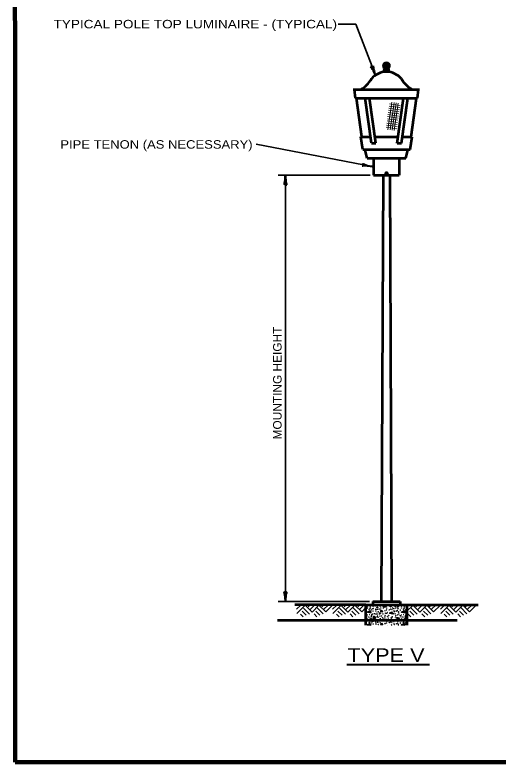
# Model space of a CAD drawing. Extents: x -20 to 693, y -19 to 435.
# Drawn here: x 28 to 170.8, y -9.1 to 211.7 of the extents above; entities that cross this region are included whole.
import ezdxf
from ezdxf.enums import TextEntityAlignment as Align

# ---------------------------------------------------------------- set-up
doc = ezdxf.new("R2010")
doc.units = 0
doc.layers.add('1', color=7, linetype='Continuous', lineweight=53)

msp = doc.modelspace()

# ---------------------------------------------------------------- hatches: boundary and pattern name
at = {"layer": '1'}
for points in [[(138.833, 196.724, 1), (136.756, 196.724, 1)], [(138.076, 164.899, 1), (137.588, 164.899, 1)]]:
    msp.add_hatch(color=256, dxfattribs=at).paths.add_polyline_path(points)

# ---------------------------------------------------------------- linework, layer by layer
at = {"layer": '1', "lineweight": 35}
for p, q in [((128.705, 209.006), (123.541, 209.006)), ((128.705, 209.006), (134.529, 193.909)), ((133.549, 166.911), (99.249, 173.552)), ((133.004, 164.369), (105.741, 164.369)), ((107.922, 38.361), (107.922, 164.369)), ((132.741, 38.361), (105.741, 38.361)), ((112.482, 37.324), (111.241, 36.083)), ((113.817, 37.324), (111.353, 34.861)), ((112.839, 35.519), (114.042, 34.315)), ((113.271, 36.421), (115.02, 34.691)), ((113.723, 37.324), (115.791, 35.255)), ((115.152, 37.324), (114.625, 36.778)), ((116.506, 37.324), (115.208, 36.026)), ((117.841, 37.324), (115.791, 35.255)), ((116.919, 35.575), (118.123, 34.372)), ((117.352, 36.478), (119.082, 34.748)), ((117.841, 37.324), (119.853, 35.312)), ((119.176, 37.324), (118.687, 36.835)), ((120.529, 37.324), (119.288, 36.083)), ((121.865, 37.324), (119.853, 35.312)), ((123.106, 37.324), (121.865, 36.083)), ((124.441, 37.324), (121.977, 34.861)), ((123.463, 35.519), (124.666, 34.315)), ((123.895, 36.421), (125.644, 34.691)), ((124.347, 37.324), (126.415, 35.255)), ((125.776, 37.324), (125.249, 36.778)), ((127.13, 37.324), (125.832, 36.026)), ((128.465, 37.324), (126.415, 35.255)), ((127.543, 35.575), (128.747, 34.372)), ((127.976, 36.478), (129.706, 34.748)), ((128.465, 37.324), (130.477, 35.312)), ((129.8, 37.324), (129.311, 36.835)), ((131.154, 37.324), (129.912, 36.083)), ((131.741, 36.576), (130.477, 35.312)), ((141.085, 36.615), (140.861, 37.361)), ((144.354, 37.324), (143.861, 36.831)), ((145.689, 37.324), (143.861, 35.496)), ((144.711, 35.519), (145.914, 34.315)), ((145.143, 36.421), (146.892, 34.691)), ((145.595, 37.324), (147.663, 35.255)), ((147.024, 37.324), (146.497, 36.778)), ((148.378, 37.324), (147.08, 36.026)), ((149.713, 37.324), (147.663, 35.255)), ((148.791, 35.575), (149.995, 34.372)), ((149.224, 36.478), (150.954, 34.748)), ((149.713, 37.324), (151.725, 35.312)), ((151.048, 37.324), (150.559, 36.835)), ((152.401, 37.324), (151.16, 36.083)), ((153.737, 37.324), (151.725, 35.312)), ((154.978, 37.324), (153.737, 36.083)), ((156.313, 37.324), (153.849, 34.861)), ((155.335, 35.519), (156.538, 34.315)), ((155.767, 36.421), (157.516, 34.691)), ((156.219, 37.324), (158.287, 35.255)), ((157.648, 37.324), (157.121, 36.778)), ((159.002, 37.324), (157.704, 36.026)), ((160.337, 37.324), (158.287, 35.255)), ((159.415, 35.575), (160.619, 34.372)), ((159.848, 36.478), (161.578, 34.748)), ((160.337, 37.324), (162.349, 35.312)), ((161.672, 37.324), (161.183, 36.835)), ((163.025, 37.324), (161.785, 36.083)), ((164.361, 37.324), (162.349, 35.312)), ((112.369, 34.654), (113.177, 33.864)), ((116.43, 34.71), (117.239, 33.901)), ((122.993, 34.654), (123.801, 33.864)), ((127.054, 34.71), (127.863, 33.901)), ((144.241, 34.654), (145.049, 33.864)), ((148.302, 34.71), (149.111, 33.901)), ((154.865, 34.654), (155.673, 33.864)), ((158.926, 34.71), (159.735, 33.901)), ((133.203, 31.361), (133.105, 31.815)), ((139.365, 31.475), (139.156, 31.361)), ((139.41, 31.361), (139.325, 31.495)), ((143.283, 31.361), (143.185, 31.815))]:
    msp.add_line(p, q, dxfattribs=at)
at = {"layer": '1'}
for p, q in [((136.851, 195.253), (138.75, 195.253)), ((136.851, 195.253), (136.851, 194.855)), ((138.75, 195.253), (138.75, 194.855)), ((127.992, 189.678), (147.609, 189.678)), ((128.625, 187.147), (128.309, 189.678)), ((146.976, 187.147), (147.293, 189.678)), ((130.522, 175.756), (128.941, 187.147)), ((133.337, 173.875), (131.496, 187.147)), ((134.614, 173.875), (132.774, 187.147)), ((140.984, 173.875), (142.827, 187.147)), ((142.262, 173.875), (144.104, 187.147)), ((145.08, 175.756), (146.66, 187.147)), ((130.831, 171.959), (130.198, 175.756)), ((130.198, 175.756), (133.076, 175.756)), ((134.354, 175.756), (141.246, 175.756)), ((142.524, 175.756), (145.403, 175.756)), ((144.77, 171.959), (145.403, 175.756)), ((133.337, 173.875), (134.614, 173.875)), ((140.984, 173.875), (142.262, 173.875)), ((130.831, 171.959), (144.77, 171.959)), ((132.086, 169.428), (131.491, 171.806)), ((143.516, 169.428), (144.11, 171.806)), ((132.086, 169.428), (143.516, 169.428)), ((134.004, 169.428), (134.004, 164.365)), ((141.598, 169.428), (141.598, 164.365)), ((134.004, 164.365), (141.598, 164.365)), ((136.781, 164.369), (136.281, 38.361)), ((138.821, 164.361), (139.321, 38.361)), ((133.741, 38.361), (141.861, 38.361)), ((133.741, 38.361), (133.741, 37.361)), ((141.861, 38.361), (141.861, 37.361)), ((131.741, 37.361), (110.741, 37.361)), ((131.741, 31.361), (131.741, 37.361)), ((143.861, 37.361), (164.861, 37.361)), ((105.614, 32.918), (158.734, 32.918))]:
    msp.add_line(p, q, dxfattribs=at)
at = {"layer": '1', "lineweight": 13}
for p, q in [((138.23, 177.835), (139.412, 185.977)), ((138.858, 177.744), (140.038, 185.886)), ((139.483, 177.654), (140.665, 185.795)), ((140.109, 177.563), (141.291, 185.705)), ((141.554, 183.109), (138.423, 183.562)), ((141.645, 183.736), (138.514, 184.189)), ((141.735, 184.362), (138.605, 184.815)), ((141.826, 184.988), (138.695, 185.441)), ((141.282, 181.231), (138.149, 181.684)), ((141.372, 181.856), (138.243, 182.311)), ((141.464, 182.483), (138.333, 182.936)), ((140.918, 178.725), (137.787, 179.179)), ((141.009, 179.351), (137.878, 179.805)), ((141.1, 179.977), (137.969, 180.431)), ((141.191, 180.604), (138.06, 181.058)), ((140.827, 178.099), (137.697, 178.553))]:
    msp.add_line(p, q, dxfattribs=at)
at = {"layer": '1', "lineweight": 40}
msp.add_line((126.043, 19.789), (150.482, 19.789), dxfattribs=at)
at = {"layer": '1', "lineweight": 158}
msp.add_line((687.723, -9.063), (28.056, -9.063), dxfattribs=at)
msp.add_lwpolyline([(687.723, 429.353), (27.973, 429.27), (28.056, -9.063)], dxfattribs=at)
at = {"layer": '1'}
for points in [[(128.625, 187.147), (132.747, 187.147), (144.124, 187.147), (146.976, 187.147)], [(131.741, 37.361), (143.861, 37.361), (143.861, 31.361)]]:
    msp.add_lwpolyline(points, dxfattribs=at)
at = {"layer": '1', "lineweight": 35}
for points in [[(133.105, 35.655), (132.165, 35.275), (133.205, 35.155), (133.105, 35.615)], [(134.575, 37.361), (133.825, 36.995), (133.877, 37.361)], [(136.465, 35.795), (136.085, 35.395), (136.665, 35.355), (136.465, 35.755)], [(141.106, 37.361), (141.625, 37.255), (141.065, 36.655)], [(143.185, 35.655), (142.245, 35.275), (143.285, 35.155), (143.185, 35.615)], [(133.985, 34.015), (134.685, 33.615), (133.825, 33.195), (133.945, 34.035)], [(139.365, 35.275), (138.705, 34.915), (139.685, 34.735), (139.325, 35.295)], [(141.085, 32.815), (140.845, 33.615), (141.625, 33.455), (141.065, 32.855)], [(133.105, 31.855), (132.165, 31.475), (133.149, 31.361)], [(136.465, 31.995), (136.085, 31.595), (136.665, 31.555), (136.465, 31.955)], [(143.185, 31.855), (142.245, 31.475), (143.229, 31.361)]]:
    msp.add_lwpolyline(points, dxfattribs=at)
for points in [[(136.745, 37.035), (137.785, 36.915), (137.105, 36.675)], [(136.745, 33.235), (137.785, 33.115), (137.105, 32.875)]]:
    msp.add_lwpolyline(points, close=True, dxfattribs=at)
for centre, radius in [((137.794, 196.724), 1.038), ((131.815, 35.852), 0.0265), ((132.146, 36.484), 0.0265), ((132.212, 37.027), 0.0265), ((132.703, 35.945), 0.0265), ((132.915, 36.258), 0.0265), ((132.994, 37.279), 0.0265), ((133.007, 36.762), 0.0265), ((133.286, 37.213), 0.0265), ((133.339, 35.905), 0.0265), ((133.617, 36.232), 0.0265), ((133.869, 35.534), 0.0265), ((133.895, 36.351), 0.0265), ((134.638, 37.067), 0.0265), ((134.664, 35.998), 0.0265), ((134.677, 36.165), 0.0265), ((134.704, 35.547), 0.0265), ((134.969, 36.669), 0.0265), ((135.168, 36.051), 0.0265), ((135.194, 36.669), 0.0265), ((135.38, 35.362), 0.0265), ((135.658, 36.179), 0.0265), ((135.89, 37.038), 0.0265), ((136.024, 35.865), 0.0265), ((136.116, 37.054), 0.0265), ((136.116, 36.457), 0.0265), ((136.925, 36.417), 0.0265), ((137.362, 35.653), 0.0265), ((137.813, 35.826), 0.0265), ((137.919, 36.338), 0.0265), ((138.356, 37.279), 0.0265), ((138.621, 35.918), 0.0265), ((138.952, 36.868), 0.0265), ((139.019, 36.112), 0.0265), ((139.271, 37.014), 0.0265), ((139.416, 35.985), 0.0265), ((139.615, 36.47), 0.0265), ((139.973, 36.271), 0.0265), ((140.039, 35.587), 0.0265), ((140.198, 35.375), 0.0265), ((140.371, 36.842), 0.0265), ((140.556, 36.417), 0.0265), ((140.715, 35.587), 0.0265), ((141.113, 35.746), 0.0265), ((141.205, 36.271), 0.0265), ((141.895, 35.852), 0.0265), ((142.226, 36.484), 0.0265), ((142.292, 37.027), 0.0265), ((142.783, 35.945), 0.0265), ((142.995, 36.258), 0.0265), ((143.074, 37.279), 0.0265), ((143.087, 36.762), 0.0265), ((143.366, 37.213), 0.0265), ((143.419, 35.905), 0.0265), ((143.697, 36.232), 0.0265), ((131.775, 34.208), 0.0265), ((132.053, 33.837), 0.0265), ((132.186, 34.434), 0.0265), ((132.212, 33.227), 0.0265), ((132.57, 33.81), 0.0265), ((132.835, 34.526), 0.0265), ((132.994, 33.479), 0.0265), ((133.233, 35.017), 0.0265), ((133.286, 33.413), 0.0265), ((133.299, 33.89), 0.0265), ((133.365, 34.195), 0.0265), ((133.471, 34.513), 0.0265), ((133.75, 34.685), 0.0265), ((134.28, 34.805), 0.0265), ((134.638, 33.267), 0.0265), ((134.73, 34.659), 0.0265), ((135.048, 34.951), 0.0265), ((135.101, 33.996), 0.0265), ((135.154, 34.553), 0.0265), ((135.327, 33.704), 0.0265), ((135.738, 34.964), 0.0265), ((135.751, 34.646), 0.0265), ((135.89, 33.238), 0.0265), ((135.91, 34.049), 0.0265), ((135.971, 34.884), 0.0265), ((136.116, 33.254), 0.0265), ((136.328, 34.102), 0.0265), ((136.66, 33.585), 0.0265), ((136.752, 34.712), 0.0265), ((137.336, 33.81), 0.0265), ((137.389, 34.208), 0.0265), ((137.468, 34.937), 0.0265), ((137.813, 34.898), 0.0265), ((138.078, 33.996), 0.0265), ((138.131, 35.136), 0.0265), ((138.356, 33.479), 0.0265), ((138.475, 34.208), 0.0265), ((139.231, 33.704), 0.0265), ((139.271, 33.214), 0.0265), ((139.642, 33.877), 0.0265), ((140.039, 34.845), 0.0265), ((140.41, 33.638), 0.0265), ((140.424, 34.752), 0.0265), ((140.543, 34.182), 0.0265), ((141.086, 34.42), 0.0265), ((141.338, 35.282), 0.0265), ((141.391, 35.282), 0.0265), ((141.457, 34.699), 0.0265), ((141.855, 34.208), 0.0265), ((142.133, 33.837), 0.0265), ((142.266, 34.434), 0.0265), ((142.292, 33.227), 0.0265), ((142.65, 33.81), 0.0265), ((142.915, 34.526), 0.0265), ((143.074, 33.479), 0.0265), ((143.313, 35.017), 0.0265), ((143.366, 33.413), 0.0265), ((143.379, 33.89), 0.0265), ((143.445, 34.195), 0.0265), ((143.551, 34.513), 0.0265), ((143.83, 34.685), 0.0265), ((131.815, 32.052), 0.0265), ((132.146, 32.684), 0.0265), ((132.703, 32.145), 0.0265), ((132.915, 32.458), 0.0265), ((133.007, 32.962), 0.0265), ((133.339, 32.105), 0.0265), ((133.617, 32.432), 0.0265), ((133.869, 31.734), 0.0265), ((133.895, 32.551), 0.0265), ((134.664, 32.198), 0.0265), ((134.677, 32.365), 0.0265), ((134.704, 31.747), 0.0265), ((134.969, 32.869), 0.0265), ((135.168, 32.251), 0.0265), ((135.194, 32.869), 0.0265), ((135.38, 31.562), 0.0265), ((135.658, 32.379), 0.0265), ((136.024, 32.065), 0.0265), ((136.116, 32.657), 0.0265), ((136.925, 32.617), 0.0265), ((137.362, 31.853), 0.0265), ((137.813, 32.026), 0.0265), ((137.919, 32.538), 0.0265), ((138.621, 32.118), 0.0265), ((138.952, 33.068), 0.0265), ((139.019, 32.312), 0.0265), ((139.416, 32.185), 0.0265), ((139.615, 32.67), 0.0265), ((139.973, 32.471), 0.0265), ((140.039, 31.787), 0.0265), ((140.198, 31.575), 0.0265), ((140.371, 33.042), 0.0265), ((140.556, 32.617), 0.0265), ((140.715, 31.787), 0.0265), ((141.113, 31.946), 0.0265), ((141.205, 32.471), 0.0265), ((141.338, 31.482), 0.0265), ((141.391, 31.482), 0.0265), ((141.895, 32.052), 0.0265), ((142.226, 32.684), 0.0265), ((142.783, 32.145), 0.0265), ((142.995, 32.458), 0.0265), ((143.087, 32.962), 0.0265), ((143.419, 32.105), 0.0265), ((143.697, 32.432), 0.0265)]:
    msp.add_circle(centre, radius, dxfattribs=at)
at = {"layer": '1'}
msp.add_circle((137.832, 164.899), 0.244, dxfattribs=at)
for centre, radius, start, end in [((137.801, 189.198), 5.736, 39.44091, 140.55908), ((136.321, 195.574), 0.906, 339.18067, 20.81934), ((139.28, 195.584), 0.906, 159.18066, 200.81933), ((125.493, 197.556), 9.181, 300.89581, 329.10419), ((150.109, 197.556), 9.181, 210.89581, 239.10419)]:
    msp.add_arc(centre, radius, start, end, dxfattribs=at)
at = {"layer": '1', "lineweight": 35}
for centre, start, end in [((136.66, 37.385), 244.04528, 295.95472), ((138.131, 31.336), 71.31058, 108.68942)]:
    msp.add_arc(centre, 0.0265, start, end, dxfattribs=at)
at = {"layer": '1', "lineweight": 40}
for centre, major_axis, ratio, start_param, end_param in [((134.323, 195.031), (-0.468, 1.702), 0.07063, 6.2823074, 8.5597026), ((133.879, 194.828), (0.788, -1.61), 0.122415, 0.8963533, 3.1415927), ((132.489, 167.331), (-1.691, 0.506), 0.07063, 6.2823074, 8.5597026), ((132.489, 167.331), (-1.691, 0.506), 0.07063, 6.2823074, 8.5597026), ((132.425, 166.847), (1.783, -0.186), 0.122415, 0.8963533, 3.1415927), ((132.425, 166.847), (1.783, -0.186), 0.122415, 0.8963533, 3.1415927), ((107.71, 163.249), (0.176, 1.756), 0.07063, 3.1407148, 5.41811), ((108.198, 163.278), (-0.156, 1.786), 0.122415, 0.8963533, 3.1415927), ((107.646, 39.453), (0.156, -1.786), 0.122415, 0.8963533, 3.1415927), ((108.134, 39.482), (-0.176, -1.756), 0.07063, 3.1407148, 5.41811)]:
    msp.add_ellipse(centre, major_axis=major_axis, ratio=ratio, start_param=start_param, end_param=end_param, dxfattribs=at)

# ---------------------------------------------------------------- texts
at = {"layer": '1', "width": 1.2}
msp.add_text('TYPICAL POLE TOP LUMINAIRE - (TYPICAL)', height=2.5, dxfattribs=at).set_placement((39.382, 207.78))
at = {"layer": '1'}
for s, height, width, p in [('PIPE TENON (AS NECESSARY)', 2.5, 1.15, (69.812, 172.222)), ('TYPE V', 4, 1.2, (137.664, 20.555))]:
    msp.add_text(s, height=height, dxfattribs=dict(at, width=width)).set_placement(p, align=Align.CENTER)
at = {"layer": '1', "width": 1.05}
msp.add_text('MOUNTING HEIGHT', height=2.5, rotation=90, dxfattribs=at).set_placement((106.794, 86.283))

doc.saveas('drawing.dxf')
